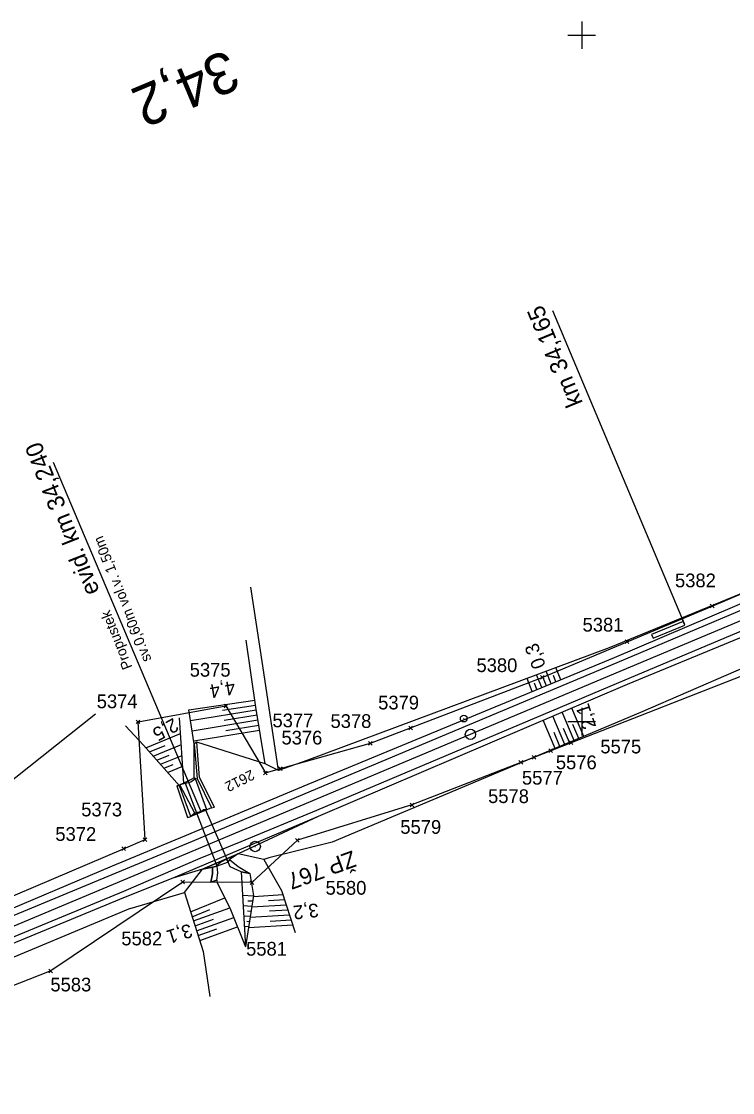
# Model space of a CAD drawing. Extents: x -805730 to -804640, y -1150889 to -1150366.
# Drawn here: x -805081.6 to -804978, y -1150654 to -1150498 of the extents above; entities that cross this region are included whole.
import ezdxf

# ---------------------------------------------------------------- set-up
doc = ezdxf.new("R2010")
doc.units = 0
for name, color, linetype in [('0381KM032-037P - Vrstva 1', 7, 'Continuous'), ('0381KM032-037P - Vrstva 16', 7, 'Continuous'), ('0381KM032-037P - Vrstva 17', 7, 'Continuous'), ('0381KM032-037P - Vrstva 19', 7, 'Continuous'), ('0381KM032-037P - Vrstva 4', 7, 'Continuous'), ('0381KM032-037P - Vrstva 48', 7, 'Continuous'), ('0381KM032-037P - Vrstva 49', 7, 'Continuous'), ('0381KM032-037P - Vrstva 57', 7, 'Continuous'), ('0381KM032-037P - Vrstva 7', 7, 'Continuous'), ('0381KM032-037P - Vrstva 9', 7, 'Continuous'), ('krizky_1000 - Vrstva 1', 7, 'Continuous'), ('szdc - hran DP', 7, 'Continuous'), ('szdc - szdc_cislo', 7, 'Continuous'), ('szdc - szdc_krizek', 7, 'Continuous'), ('vyt_sit - stávající', 7, 'Continuous')]:
    doc.layers.add(name, color=color, linetype=linetype)

msp = doc.modelspace()

# ---------------------------------------------------------------- linework, layer by layer
at = {"layer": '0381KM032-037P - Vrstva 1'}
for points in [[(-804910.33, -1150557.31), (-804952.12, -1150574.92), (-804994.42, -1150592.71), (-805038.63, -1150611.27), (-805057.71, -1150619.3), (-805074.24, -1150626.27)], [(-805074.24, -1150626.27), (-805091.51, -1150633.48)]]:
    msp.add_lwpolyline(points, dxfattribs=at)
at = {"layer": '0381KM032-037P - Vrstva 16'}
for points in [[(-805053.78, -1150621.21), (-805053.78, -1150622.18), (-805053.99, -1150623.39), (-805053.13, -1150623.09), (-805053, -1150622.04), (-805053.1, -1150621.07), (-805053.78, -1150621.21)], [(-805051.5, -1150620.47), (-805051.28, -1150620.09), (-805050.01, -1150621.11), (-805048.33, -1150622.13), (-805049.58, -1150621.86), (-805051.2, -1150621.14), (-805051.5, -1150620.47)]]:
    msp.add_lwpolyline(points, dxfattribs=at)
at = {"layer": '0381KM032-037P - Vrstva 17'}
for points in [[(-804868.16, -1150549.89), (-804869.02, -1150549.09), (-804889.78, -1150557.12), (-804908.89, -1150563.18), (-804949.8, -1150580.61), (-804991.45, -1150598.69), (-805036.34, -1150617.58)], [(-804906.51, -1150551), (-804923.2, -1150557.6), (-804942.52, -1150566.83), (-804953.3, -1150571.71), (-804995.99, -1150589.23), (-805040.03, -1150605.68), (-805044.15, -1150607.13)], [(-805044.15, -1150607.13), (-805046.42, -1150591.86), (-805048.16, -1150580.41)], [(-805070.8, -1150598.9), (-805121.06, -1150638.84), (-805152.76, -1150646.7), (-805170.92, -1150650.08), (-805194.39, -1150650.05), (-805213.2, -1150651.26), (-805221.79, -1150652.33), (-805228.79, -1150654.03)]]:
    msp.add_lwpolyline(points, dxfattribs=at)
at = {"layer": '0381KM032-037P - Vrstva 19'}
for p, q in [((-805076.95, -1150562.18), (-805055.39, -1150613.19)), ((-805056.34, -1150613.34), (-805058.5, -1150609.19)), ((-805054.78, -1150612.85), (-805056.06, -1150613.31)), ((-805053.1, -1150621.07), (-805056.06, -1150613.31)), ((-805054.78, -1150612.85), (-805051.5, -1150620.47)), ((-805051.5, -1150620.47), (-805053.1, -1150621.07))]:
    msp.add_line(p, q, dxfattribs=at)
for points in [[(-805056.22, -1150608.31), (-805056.45, -1150608.2), (-805056.44, -1150603.21)], [(-805053.89, -1150612.54), (-805053.47, -1150612.44), (-805055.64, -1150608.13), (-805056.05, -1150602.98), (-805056.44, -1150603.21), (-805056.02, -1150608.26)], [(-805056.45, -1150608.2), (-805056.99, -1150608.48), (-805057.93, -1150608.98), (-805058.5, -1150609.19)], [(-805054.6, -1150612.84), (-805056.22, -1150608.31), (-805056.92, -1150608.82), (-805057.71, -1150609)], [(-805056.22, -1150608.31), (-805056.02, -1150608.26), (-805053.89, -1150612.54), (-805056.9, -1150613.84)], [(-805056.06, -1150613.31), (-805057.71, -1150609), (-805058.5, -1150609.19), (-805058.59, -1150609.33), (-805058.96, -1150609.37), (-805057.41, -1150613.95), (-805056.9, -1150613.84), (-805058.59, -1150609.33)], [(-805055.86, -1150613.18), (-805056.06, -1150613.31), (-805056.34, -1150613.34), (-805056.9, -1150613.84)], [(-805054.6, -1150612.84), (-805054.78, -1150612.85), (-805055.1, -1150612.83)], [(-805055.21, -1150621.51), (-805053.78, -1150621.21), (-805055.21, -1150621.51), (-805050.01, -1150619.25), (-805051.28, -1150620.09), (-805051.5, -1150620.47), (-805051.69, -1150620.12)], [(-805053.78, -1150621.21), (-805053.1, -1150621.07), (-805052.93, -1150620.83)]]:
    msp.add_lwpolyline(points, dxfattribs=at)
for centre, major_axis, ratio, start_param, end_param in [((-805055.48, -1150613.01), (0.389, 0.172), 0.155868, 3.060843, 6.493994), ((-805052.24, -1150620.62), (-0.751, -0.434), 0.315901, 3.723079, 5.657425)]:
    msp.add_ellipse(centre, major_axis=major_axis, ratio=ratio, start_param=start_param, end_param=end_param, dxfattribs=at)
at = {"layer": '0381KM032-037P - Vrstva 4'}
for points in [[(-804864.42, -1150538.53), (-804893.06, -1150548.77), (-804911.6, -1150556.2), (-804952.82, -1150573.68), (-804994.86, -1150591.44), (-805039.39, -1150610.13), (-805056.71, -1150617.44), (-805097.6, -1150634.39)], [(-804872.17, -1150539.66), (-804893.72, -1150547.52), (-804911.96, -1150555), (-804952.93, -1150572.63), (-804995.29, -1150590.69), (-805039.86, -1150609.18), (-805057.83, -1150616.69), (-805068.36, -1150621.07), (-805097.92, -1150633.57)], [(-804862.73, -1150542.41), (-804863.39, -1150541.46), (-804892.29, -1150551.48), (-804910.22, -1150558.86), (-804951.61, -1150576.23), (-804993.7, -1150593.96), (-805038.63, -1150612.92), (-805049.62, -1150617.53), (-805055.59, -1150619.94), (-805066.74, -1150624.75), (-805096.44, -1150637.01)], [(-804864.94, -1150543.15), (-804869.59, -1150544.8), (-804891.93, -1150552.26), (-804909.8, -1150559.87), (-804951.24, -1150577.2), (-804993.38, -1150594.6), (-805038.39, -1150613.8), (-805059.54, -1150622.79), (-805066.49, -1150625.57), (-805096.25, -1150637.87)]]:
    msp.add_lwpolyline(points, dxfattribs=at)
at = {"layer": '0381KM032-037P - Vrstva 48'}
for p, q in [((-805004.43, -1150594.48), (-805005.15, -1150592.66)), ((-805003.04, -1150593.91), (-805003.74, -1150592.13)), ((-805007.2, -1150595.63), (-805007.96, -1150593.7)), ((-805006.51, -1150595.34), (-805006.88, -1150594.39)), ((-805005.82, -1150595.05), (-805006.56, -1150593.18)), ((-805005.12, -1150594.77), (-805005.49, -1150593.84)), ((-805003.74, -1150594.19), (-805004.09, -1150593.29)), ((-805047.61, -1150596.92), (-805057.19, -1150598.31)), ((-805047.5, -1150597.67), (-805052.29, -1150598.36)), ((-805047.4, -1150598.32), (-805056.95, -1150599.89)), ((-805047.27, -1150599.06), (-805052.05, -1150599.84)), ((-805002.47, -1150603.33), (-805004.21, -1150599.21)), ((-805001.09, -1150602.75), (-805002.83, -1150598.63)), ((-804999.71, -1150602.17), (-805001.45, -1150598.04)), ((-805047.15, -1150599.8), (-805056.72, -1150601.37)), ((-805047.02, -1150600.54), (-805051.82, -1150601.32)), ((-805003.86, -1150603.91), (-805005.59, -1150599.8)), ((-805000.4, -1150602.46), (-805001.27, -1150600.4)), ((-805063.45, -1150603.82), (-805058.4, -1150601.75)), ((-805046.9, -1150601.28), (-805056.5, -1150602.85)), ((-805003.17, -1150603.62), (-805004.03, -1150601.56)), ((-805001.78, -1150603.04), (-805002.65, -1150600.98)), ((-805062.93, -1150604.42), (-805060.64, -1150603.48)), ((-805062.4, -1150605.02), (-805058.3, -1150603.33)), ((-805061.88, -1150605.61), (-805060.06, -1150604.86)), ((-805061.35, -1150606.21), (-805058.2, -1150604.91)), ((-805060.83, -1150606.8), (-805059.49, -1150606.25)), ((-805060.3, -1150607.4), (-805058.09, -1150606.49)), ((-805056.95, -1150627.71), (-805051.95, -1150625.67)), ((-805047.79, -1150625.42), (-805049.38, -1150625.34)), ((-805043.49, -1150625.24), (-805047.8, -1150625.5)), ((-805056.72, -1150628.43), (-805054.17, -1150627.38)), ((-805056.53, -1150629.02), (-805051.22, -1150627.12)), ((-805048.02, -1150626.91), (-805049.29, -1150626.85)), ((-805047.91, -1150626.17), (-805048.62, -1150626.13)), ((-805043.02, -1150626.71), (-805048.04, -1150627.02)), ((-805043.25, -1150625.97), (-805045.59, -1150626.11)), ((-805042.78, -1150627.45), (-805045.47, -1150627.61)), ((-805056.31, -1150629.74), (-805053.62, -1150628.78)), ((-805056.08, -1150630.46), (-805050.66, -1150628.52)), ((-805048.26, -1150628.4), (-805049.2, -1150628.36)), ((-805048.14, -1150627.66), (-805048.69, -1150627.63)), ((-805042.54, -1150628.18), (-805048.28, -1150628.53)), ((-805042.3, -1150628.92), (-805045.35, -1150629.11)), ((-805055.86, -1150631.17), (-805053.12, -1150630.19)), ((-805055.63, -1150631.89), (-805050.1, -1150629.91)), ((-805048.49, -1150629.89), (-805049.11, -1150629.86)), ((-805048.37, -1150629.15), (-805048.77, -1150629.13)), ((-805042.06, -1150629.66), (-805048.51, -1150630.05))]:
    msp.add_line(p, q, dxfattribs=at)
at = {"layer": '0381KM032-037P - Vrstva 49'}
for p, q in [((-805056.44, -1150603.21), (-805057.2, -1150598.28)), ((-805057.93, -1150608.98), (-805058.55, -1150599.44)), ((-805056.05, -1150602.98), (-805056.44, -1150603.21)), ((-805044.15, -1150607.13), (-805046.07, -1150606.17)), ((-805049.58, -1150621.86), (-805048.94, -1150632.8)), ((-805049.58, -1150621.86), (-805048.33, -1150622.13))]:
    msp.add_line(p, q, dxfattribs=at)
for points in [[(-804871.36, -1150538.86), (-804872.17, -1150539.66), (-804893.72, -1150547.52), (-804911.96, -1150555), (-804952.93, -1150572.63), (-804995.29, -1150590.69), (-805039.86, -1150609.18), (-805057.83, -1150616.69), (-805068.36, -1150621.07), (-805097.92, -1150633.57)], [(-804906.51, -1150551), (-804923.2, -1150557.6), (-804942.52, -1150566.83), (-804953.3, -1150571.71), (-804995.99, -1150589.23), (-805040.03, -1150605.68), (-805044.15, -1150607.13)], [(-804889.78, -1150557.12), (-804908.89, -1150563.18), (-804949.8, -1150580.61), (-804991.45, -1150598.69), (-805036.34, -1150617.58)], [(-804909.8, -1150559.87), (-804951.24, -1150577.2), (-804993.38, -1150594.6), (-805038.39, -1150613.8), (-805050.01, -1150619.25), (-805055.21, -1150621.51), (-805059.54, -1150622.79), (-805066.49, -1150625.57), (-805096.25, -1150637.87)], [(-805046.07, -1150606.17), (-805047.47, -1150597.89), (-805048.87, -1150588.15)], [(-805070.8, -1150598.9), (-805121.06, -1150638.84), (-805152.76, -1150646.7), (-805170.92, -1150650.08), (-805194.39, -1150650.05), (-805213.2, -1150651.26), (-805221.79, -1150652.33), (-805228.79, -1150654.03)], [(-805058.59, -1150609.33), (-805063.79, -1150603.44), (-805066.42, -1150600.59)], [(-805046.07, -1150606.17), (-805056.05, -1150602.98)], [(-805058.59, -1150609.33), (-805058.5, -1150609.19), (-805057.93, -1150608.98)], [(-805036.34, -1150617.58), (-805045.56, -1150619.85), (-805046.28, -1150620.1), (-805050.01, -1150619.25)], [(-805053.13, -1150623.09), (-805053.99, -1150623.39), (-805053.78, -1150622.18), (-805053.78, -1150621.21), (-805055.21, -1150621.51)], [(-805046.28, -1150620.1), (-805043.7, -1150624.61), (-805041.72, -1150630.72)], [(-805065.73, -1150627.22), (-805057.84, -1150624.88), (-805055.21, -1150621.51)], [(-805048.33, -1150622.13), (-805047.78, -1150625.31), (-805048.94, -1150632.8)], [(-805053.13, -1150623.09), (-805053.07, -1150623.46), (-805051.23, -1150627.1), (-805048.94, -1150632.8)], [(-805057.84, -1150624.88), (-805055.13, -1150633.48), (-805054.13, -1150640.03)], [(-805065.73, -1150627.22), (-805095.53, -1150639.67)]]:
    msp.add_lwpolyline(points, dxfattribs=at)
at = {"layer": '0381KM032-037P - Vrstva 7'}
msp.add_line((-805017.22, -1150599.55), (-805017.12, -1150599.55), dxfattribs=at)
for centre, radius in [((-805017.17, -1150599.55), 0.5), ((-805016.2, -1150601.85), 0.75)]:
    msp.add_circle(centre, radius, dxfattribs=at)
at = {"layer": '0381KM032-037P - Vrstva 9'}
for p, q in [((-805004.24, -1150540.13), (-804985.09, -1150585.68)), ((-804985.2, -1150585.4), (-804985.43, -1150584.85)), ((-804985.2, -1150585.4), (-804989.83, -1150587.31)), ((-804989.6, -1150587.86), (-804984.97, -1150585.96)), ((-804984.97, -1150585.96), (-804985.2, -1150585.4)), ((-804989.83, -1150587.31), (-804989.6, -1150587.86))]:
    msp.add_line(p, q, dxfattribs=at)
at = {"layer": 'krizky_1000 - Vrstva 1'}
for points in [[(-805000, -1150498), (-805000, -1150502)], [(-805002, -1150500), (-804998, -1150500)], [(-805000, -1150598), (-805000, -1150602)], [(-805002, -1150600), (-804998, -1150600)]]:
    msp.add_lwpolyline(points, dxfattribs=at)
at = {"layer": 'szdc - hran DP'}
for p, q in [((-804981, -1150583.16), (-804968.41, -1150577.86)), ((-804993.4, -1150588.37), (-804981, -1150583.16)), ((-805005.74, -1150593.57), (-804993.4, -1150588.37)), ((-804973.16, -1150591.99), (-805001.53, -1150603.08)), ((-805024.92, -1150600.92), (-805005.74, -1150593.57)), ((-805064.61, -1150600.03), (-805051.81, -1150597.72)), ((-805051.81, -1150597.72), (-805046.06, -1150607.46)), ((-805063.58, -1150617.18), (-805064.61, -1150600.03)), ((-805030.76, -1150603.16), (-805024.92, -1150600.92)), ((-805043.88, -1150606.84), (-805030.76, -1150603.16)), ((-805001.53, -1150603.08), (-805004.51, -1150604.24)), ((-805006.96, -1150605.2), (-805008.86, -1150605.94)), ((-805004.51, -1150604.24), (-805006.96, -1150605.2)), ((-805046.06, -1150607.46), (-805043.88, -1150606.84)), ((-805008.86, -1150605.94), (-805024.72, -1150612.14)), ((-805024.72, -1150612.14), (-805041.4, -1150617.28)), ((-805066.7, -1150618.51), (-805063.58, -1150617.18)), ((-805041.4, -1150617.28), (-805048.02, -1150623.43)), ((-805096.7, -1150631.27), (-805066.7, -1150618.51)), ((-805058.1, -1150623.37), (-805077.33, -1150636.32)), ((-805048.02, -1150623.43), (-805058.1, -1150623.37)), ((-805077.33, -1150636.32), (-805095.21, -1150643.26))]:
    msp.add_line(p, q, dxfattribs=at)
at = {"layer": 'szdc - szdc_krizek'}
for p, q in [((-804980.73, -1150583.43), (-804981.27, -1150582.9)), ((-804981.27, -1150583.43), (-804980.73, -1150582.9)), ((-804993.14, -1150588.64), (-804993.67, -1150588.1)), ((-804993.67, -1150588.64), (-804993.14, -1150588.1)), ((-805005.47, -1150593.83), (-805006.01, -1150593.3)), ((-805006.01, -1150593.83), (-805005.47, -1150593.3)), ((-805051.55, -1150597.99), (-805052.08, -1150597.46)), ((-805052.08, -1150597.99), (-805051.55, -1150597.46)), ((-805064.34, -1150600.29), (-805064.88, -1150599.77)), ((-805064.88, -1150600.29), (-805064.34, -1150599.77)), ((-805024.66, -1150601.19), (-805025.19, -1150600.66)), ((-805025.19, -1150601.19), (-805024.66, -1150600.66)), ((-805030.49, -1150603.43), (-805031.03, -1150602.9)), ((-805031.03, -1150603.43), (-805030.49, -1150602.9)), ((-805004.24, -1150604.51), (-805004.78, -1150603.98)), ((-805004.78, -1150604.51), (-805004.24, -1150603.98)), ((-805001.27, -1150603.34), (-805001.8, -1150602.81)), ((-805001.8, -1150603.34), (-805001.27, -1150602.81)), ((-805006.7, -1150605.47), (-805007.23, -1150604.94)), ((-805007.23, -1150605.47), (-805006.7, -1150604.94)), ((-805045.8, -1150607.73), (-805046.33, -1150607.2)), ((-805046.33, -1150607.73), (-805045.8, -1150607.2)), ((-805043.61, -1150607.1), (-805044.15, -1150606.57)), ((-805044.15, -1150607.1), (-805043.61, -1150606.57)), ((-805008.59, -1150606.21), (-805009.13, -1150605.68)), ((-805009.13, -1150606.21), (-805008.59, -1150605.68)), ((-805024.46, -1150612.41), (-805024.99, -1150611.88)), ((-805024.99, -1150612.41), (-805024.46, -1150611.88)), ((-805063.32, -1150617.45), (-805063.85, -1150616.92)), ((-805063.85, -1150617.45), (-805063.32, -1150616.92)), ((-805041.14, -1150617.54), (-805041.67, -1150617.02)), ((-805041.67, -1150617.54), (-805041.14, -1150617.02)), ((-805066.44, -1150618.78), (-805066.97, -1150618.25)), ((-805066.97, -1150618.78), (-805066.44, -1150618.25)), ((-805057.83, -1150623.64), (-805058.37, -1150623.1)), ((-805058.37, -1150623.64), (-805057.83, -1150623.1)), ((-805047.76, -1150623.7), (-805048.29, -1150623.17)), ((-805048.29, -1150623.7), (-805047.76, -1150623.17)), ((-805077.07, -1150636.58), (-805077.6, -1150636.05)), ((-805077.6, -1150636.58), (-805077.07, -1150636.05))]:
    msp.add_line(p, q, dxfattribs=at)
at = {"layer": 'vyt_sit - stávající'}
msp.add_line((-805047.59, -1150618.19), (-805047.49, -1150618.19), dxfattribs=at)
msp.add_circle((-805047.55, -1150618.19), 0.756, dxfattribs=at)

# ---------------------------------------------------------------- texts
at = {"layer": '0381KM032-037P - Vrstva 19'}
for s, height, p in [('evid. km 34,240', 2.5, (-805070.16, -1150581.01)), ('sv.0,60m vol.v. 1,50m', 1.5, (-805062.62, -1150590.96)), ('Propustek', 1.5, (-805065.41, -1150592.06))]:
    msp.add_text(s, height=height, rotation=111.5275, dxfattribs=at).set_placement(p)
at = {"layer": '0381KM032-037P - Vrstva 48'}
for s, rotation, p in [('0,3', 110.4812, (-805005.19, -1150591.87)), ('4,4', 189.5991, (-805050.63, -1150594.02)), ('2,1', 108.1045, (-804997.87, -1150600.72)), ('2,5', 208.7064, (-805059.44, -1150599.4)), ('3,2', 186.1394, (-805038.41, -1150626.45)), ('3,1', 197.4468, (-805057.08, -1150629.39))]:
    msp.add_text(s, height=2, rotation=rotation, dxfattribs=at).set_placement(p)
at = {"layer": '0381KM032-037P - Vrstva 57'}
msp.add_text('2612', height=1.5, rotation=206.8307, dxfattribs=at).set_placement((-805048.13, -1150606.95))
at = {"layer": '0381KM032-037P - Vrstva 7'}
msp.add_text('34,2', height=6, rotation=202.7734, dxfattribs=at).set_placement((-805051.6, -1150502))
at = {"layer": '0381KM032-037P - Vrstva 9'}
msp.add_text('km 34,165', height=2.5, rotation=112.3772, dxfattribs=at).set_placement((-804999.79, -1150553.58))
at = {"layer": 'szdc - szdc_cislo'}
for s, p in [('5382', (-804986.41, -1150580.43)), ('5381', (-804999.87, -1150586.88)), ('5375', (-805057.08, -1150593.45)), ('5380', (-805015.32, -1150592.78)), ('5374', (-805070.62, -1150598.04)), ('5379', (-805029.64, -1150598.22)), ('5377', (-805045.03, -1150600.82)), ('5378', (-805036.58, -1150600.92)), ('5376', (-805043.72, -1150603.33)), ('5575', (-804997.28, -1150604.63)), ('5576', (-805003.76, -1150606.93)), ('5577', (-805008.7, -1150609.17)), ('5578', (-805013.63, -1150611.86)), ('5373', (-805072.88, -1150613.8)), ('5579', (-805026.41, -1150616.34)), ('5372', (-805076.65, -1150617.37)), ('5580', (-805037.3, -1150625.21)), ('5582', (-805067.04, -1150632.59)), ('5581', (-805048.87, -1150634.09)), ('5583', (-805077.37, -1150639.3))]:
    msp.add_text(s, height=2, dxfattribs=at).set_placement(p)
at = {"layer": 'vyt_sit - stávající'}
msp.add_text('ŽP 767', height=2.4, rotation=200, dxfattribs=at).set_placement((-805033.38, -1150618.73))

doc.saveas('drawing.dxf')
